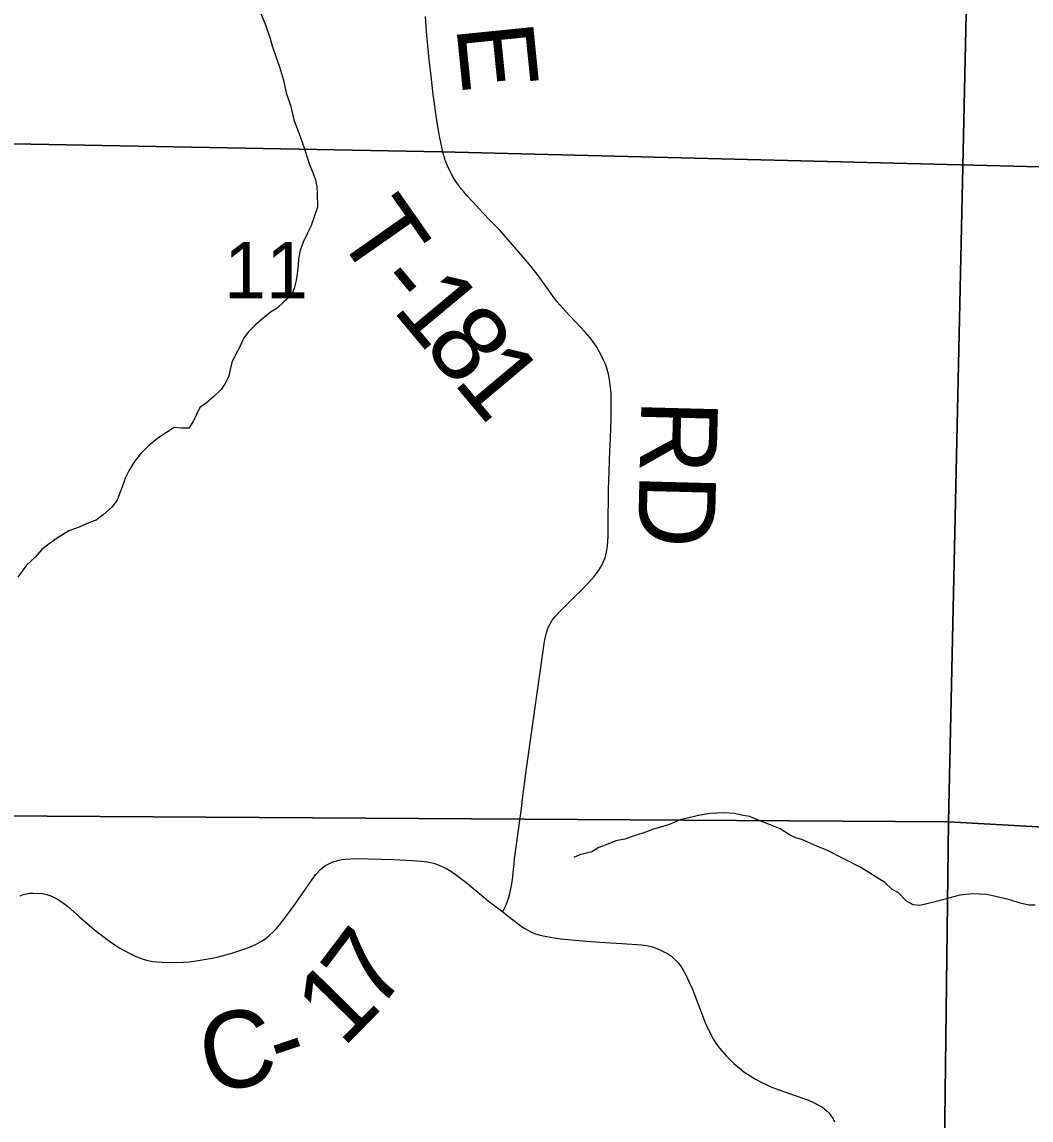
# Model space of a CAD drawing. Extents: x 0 to 34, y 0 to 22.
# Drawn here: x 13.784 to 14.532, y 16.764 to 17.577 of the extents above; entities that cross this region are included whole.
import ezdxf

# ---------------------------------------------------------------- set-up
doc = ezdxf.new("R2010")
doc.units = 0
for name, color, linetype in [('GM_X_Corporation', 7, 'Continuous'), ('GM_X_County_Road', 7, 'Continuous'), ('GM_X_County_Road_Text', 7, 'Continuous'), ('GM_X_Minor_River', 7, 'Continuous'), ('GM_X_Section_Text', 7, 'Continuous'), ('GM_X_Township_Road', 7, 'Continuous'), ('GM_X_Township_Road_Text', 7, 'Continuous')]:
    doc.layers.add(name, color=color, linetype=linetype)

msp = doc.modelspace()

# ---------------------------------------------------------------- linework, layer by layer
at = {"layer": 'GM_X_Corporation'}
for points in [[(13.27416, 17.49656), (14.09544, 17.48114), (14.72599, 17.4654), (14.75606, 17.4645), (15.84263, 17.42782), (15.88436, 17.42688), (16.48069, 17.41608), (16.48857, 17.73917), (16.51683, 18.87067), (16.5174, 18.89349), (16.54748, 18.89293), (16.75204, 18.88908), (16.75322, 19.06144), (16.75475, 19.28374), (16.76523, 20.32799), (16.7661, 20.4), (11.50006, 20.4)], [(16.44192, 14.8642), (16.44975, 15.46263), (16.45161, 15.59641), (16.46108, 16.1288), (16.46029, 16.26174), (16.46891, 16.92454), (16.47027, 17.00356), (16.4704, 17.01044), (16.48069, 17.41608), (15.88436, 17.42688), (15.84263, 17.42782), (14.75606, 17.4645), (14.72599, 17.4654), (14.09544, 17.48114), (13.27416, 17.49656)]]:
    msp.add_lwpolyline(points, dxfattribs=at)
for points in [[(13.4723, 18.00009), (14.4926, 17.9788), (14.47088, 16.98467), (13.4493, 16.99116)], [(14.4926, 17.9788), (15.50037, 17.94467), (15.48158, 16.92817), (14.47088, 16.98467)], [(13.4493, 16.99116), (14.47088, 16.98467), (14.45833, 15.96227), (13.43365, 15.97401)], [(14.47088, 16.98467), (15.48158, 16.92817), (15.46915, 15.91633), (14.45833, 15.96227)]]:
    msp.add_lwpolyline(points, close=True, dxfattribs=at)
at = {"layer": 'GM_X_County_Road'}
msp.add_lwpolyline([(13.78303, 16.92971), (13.78525, 16.93069), (13.78761, 16.93136), (13.7902, 16.93176), (13.7924, 16.9319), (13.79961, 16.93149), (13.80281, 16.93077), (13.80572, 16.92969), (13.80876, 16.92834), (13.81199, 16.92652), (13.81518, 16.92434), (13.81832, 16.92189), (13.82681, 16.91455), (13.83814, 16.90465), (13.84131, 16.90212), (13.84924, 16.89619), (13.85311, 16.89352), (13.85688, 16.89108), (13.8605, 16.88894), (13.86462, 16.88675), (13.8682, 16.88506), (13.87407, 16.8828), (13.87658, 16.88209), (13.8812, 16.88119), (13.88388, 16.88087), (13.88821, 16.88057), (13.892, 16.88046), (13.90407, 16.88065), (13.90815, 16.88096), (13.91335, 16.8816), (13.92521, 16.88367), (13.92986, 16.88466), (13.93533, 16.886), (13.9405, 16.88751), (13.94957, 16.8906), (13.95406, 16.89232), (13.95797, 16.89406), (13.96171, 16.89615), (13.96416, 16.89779), (13.96772, 16.90054), (13.97055, 16.90316), (13.97291, 16.90571), (13.97607, 16.90954), (13.981, 16.91589), (13.98645, 16.92328), (13.9915, 16.93063), (14.00099, 16.94436), (14.00208, 16.94572), (14.00576, 16.94961), (14.00721, 16.95083), (14.00919, 16.95221), (14.01174, 16.95362), (14.01408, 16.95467), (14.01646, 16.95552), (14.01919, 16.95627), (14.02139, 16.9567), (14.02396, 16.95703), (14.03145, 16.95741), (14.0598, 16.95677), (14.07342, 16.95608), (14.0804, 16.9555), (14.08491, 16.95492), (14.08921, 16.95404), (14.09157, 16.95326), (14.09676, 16.95104), (14.09973, 16.94949), (14.10257, 16.94782), (14.10537, 16.94596), (14.1113, 16.94141), (14.11439, 16.93883), (14.12496, 16.93002), (14.12982, 16.92618), (14.14054, 16.91787), (14.14348, 16.91557), (14.15301, 16.90837), (14.15446, 16.90705), (14.15692, 16.90558), (14.15916, 16.90438), (14.16196, 16.90288), (14.1642, 16.90197), (14.1673, 16.90096), (14.17044, 16.90017), (14.17875, 16.89866), (14.18362, 16.89805), (14.20271, 16.89628), (14.21244, 16.89548), (14.22885, 16.89447), (14.24001, 16.89384), (14.24364, 16.89352), (14.24721, 16.89299), (14.25052, 16.89226), (14.25355, 16.89128), (14.25653, 16.89003), (14.25994, 16.88843), (14.26256, 16.88697), (14.26576, 16.88479), (14.26834, 16.88243), (14.27047, 16.88024), (14.27226, 16.87793), (14.27432, 16.87468), (14.27641, 16.87075), (14.27848, 16.86641), (14.28104, 16.86055), (14.28341, 16.85464), (14.29086, 16.83531), (14.29195, 16.83279), (14.29491, 16.82664), (14.29675, 16.82337), (14.299, 16.81989), (14.30118, 16.81696), (14.30636, 16.81096), (14.30848, 16.80876), (14.31213, 16.80528), (14.31597, 16.80203), (14.3193, 16.79948), (14.32388, 16.79633), (14.32788, 16.79391), (14.33202, 16.79167), (14.33577, 16.78988), (14.33928, 16.78836), (14.34519, 16.78609), (14.36707, 16.77831), (14.36972, 16.7772), (14.37602, 16.77405), (14.37743, 16.77318), (14.38105, 16.77027), (14.38225, 16.76899), (14.38377, 16.76704), (14.38531, 16.76463), (14.38644, 16.76241)], dxfattribs=at)
at = {"layer": 'GM_X_Minor_River'}
for points in [[(13.96092, 17.58483), (13.96475, 17.57534), (13.9682, 17.5651), (13.96974, 17.55978), (13.97242, 17.55181), (13.97511, 17.54422), (13.97818, 17.53436), (13.98011, 17.52487), (13.98318, 17.51538), (13.98588, 17.50475), (13.99047, 17.49261), (13.99392, 17.48274), (13.99546, 17.47781), (13.99738, 17.47174), (13.99968, 17.46643), (14.00159, 17.46111), (14.00275, 17.45542), (14.00315, 17.45048), (14.00318, 17.44023), (14.00093, 17.43301), (13.9983, 17.42579), (13.99566, 17.42047), (13.99302, 17.41477), (13.99039, 17.40831), (13.98927, 17.40185), (13.98891, 17.3973), (13.98817, 17.39084), (13.98743, 17.3859), (13.98593, 17.37982), (13.98405, 17.37488), (13.97837, 17.36994), (13.97346, 17.36537), (13.96853, 17.36232), (13.96285, 17.35776), (13.95717, 17.35281), (13.95187, 17.34748), (13.94847, 17.34292), (13.94546, 17.33608), (13.94244, 17.33076), (13.93981, 17.32506), (13.93868, 17.31974), (13.93756, 17.3148), (13.93492, 17.30948), (13.9319, 17.30492), (13.92623, 17.29959), (13.92093, 17.29503), (13.916, 17.2916), (13.9111, 17.28134), (13.90808, 17.2764), (13.90239, 17.27639), (13.89707, 17.27675), (13.88571, 17.26952), (13.87851, 17.26381), (13.87208, 17.25734), (13.86717, 17.25088), (13.86339, 17.2448), (13.86113, 17.23985), (13.8585, 17.23302), (13.85474, 17.22314), (13.85096, 17.21781), (13.84453, 17.2121), (13.83922, 17.2083), (13.83429, 17.20639), (13.82671, 17.20296), (13.81913, 17.20028), (13.81117, 17.19534), (13.80435, 17.19077), (13.79905, 17.18658), (13.79414, 17.18087), (13.78771, 17.17479), (13.78128, 17.16604)], [(14.535, 16.9229), (14.53045, 16.92289), (14.52399, 16.9244), (14.51714, 16.92667), (14.51106, 16.92817), (14.50575, 16.92931), (14.49929, 16.93081), (14.48827, 16.93117), (14.47917, 16.93039), (14.46817, 16.92734), (14.46286, 16.92581), (14.45489, 16.92389), (14.44958, 16.92274), (14.44464, 16.92312), (14.4397, 16.92576), (14.4336, 16.93221), (14.42903, 16.93448), (14.4237, 16.93978), (14.41571, 16.94471), (14.40582, 16.95076), (14.38072, 16.96363), (14.37387, 16.96627), (14.36209, 16.97157), (14.35753, 16.9727), (14.35296, 16.97497), (14.34611, 16.97951), (14.33623, 16.98329), (14.32862, 16.98631), (14.32368, 16.98858), (14.31874, 16.98933), (14.31228, 16.99084), (14.30431, 16.9912), (14.29406, 16.9908), (14.28685, 16.98965), (14.27205, 16.98621), (14.26333, 16.98239), (14.25158, 16.97896), (14.24437, 16.97628), (14.23792, 16.97437), (14.2311, 16.9717), (14.22427, 16.97055), (14.21707, 16.9675), (14.21176, 16.96559), (14.20646, 16.96254), (14.19773, 16.96025), (14.19318, 16.95834)]]:
    msp.add_lwpolyline(points, dxfattribs=at)
at = {"layer": 'GM_X_Township_Road'}
for points in [[(14.08475, 17.56234), (14.08425, 17.5671), (14.08332, 17.58153)], [(14.09796, 17.47485), (14.09611, 17.48112), (14.09365, 17.49285), (14.09169, 17.50447), (14.08907, 17.52368), (14.08741, 17.53713), (14.08585, 17.55185), (14.08475, 17.56234)], [(14.15889, 17.39927), (14.15242, 17.4069), (14.14303, 17.4176), (14.13805, 17.42332), (14.13487, 17.42659), (14.1315, 17.43006), (14.12565, 17.43623), (14.12134, 17.44078), (14.11778, 17.44463), (14.11416, 17.44854), (14.1117, 17.45143), (14.10975, 17.45382), (14.10794, 17.45618), (14.10638, 17.45835), (14.10454, 17.46118), (14.10282, 17.46416), (14.10128, 17.46711), (14.09964, 17.47068), (14.09856, 17.47328), (14.09796, 17.47485)], [(14.14054, 16.91787), (14.14257, 16.92223), (14.14376, 16.92512), (14.14509, 16.92886), (14.14616, 16.93259), (14.14712, 16.93743), (14.14767, 16.94164), (14.14911, 16.95415), (14.1496, 16.95887), (14.15447, 16.99446), (14.15523, 17.00135), (14.15811, 17.02422), (14.16156, 17.04873), (14.17152, 17.11817), (14.17203, 17.12076), (14.1727, 17.12382), (14.1737, 17.12706), (14.17448, 17.12907), (14.17559, 17.13134), (14.17726, 17.13402), (14.17967, 17.13717), (14.18229, 17.14011), (14.18919, 17.14702), (14.19357, 17.15119), (14.19856, 17.15599), (14.20634, 17.16411), (14.20843, 17.16664), (14.21116, 17.17036), (14.21341, 17.17394), (14.21502, 17.177), (14.21638, 17.18021), (14.21703, 17.18227), (14.21755, 17.18457), (14.21811, 17.18904), (14.21856, 17.19631), (14.21873, 17.20335), (14.21902, 17.23098), (14.21937, 17.24416), (14.21967, 17.25264), (14.21994, 17.25938), (14.22034, 17.26877), (14.22065, 17.2768), (14.22085, 17.28263), (14.22099, 17.2927), (14.22078, 17.30171), (14.2206, 17.30471), (14.21973, 17.31227), (14.21914, 17.31536), (14.2185, 17.31803), (14.21747, 17.32147), (14.21662, 17.32381), (14.21524, 17.32689), (14.21405, 17.32957), (14.21235, 17.33277), (14.21021, 17.33638), (14.20757, 17.34029), (14.20499, 17.34365), (14.20172, 17.34749), (14.19426, 17.35551), (14.18704, 17.36317), (14.18296, 17.36771), (14.17925, 17.37221), (14.17585, 17.37677), (14.17299, 17.38085), (14.1711, 17.38355), (14.16811, 17.38767), (14.1661, 17.39044), (14.16213, 17.39545), (14.15889, 17.39927)]]:
    msp.add_lwpolyline(points, dxfattribs=at)

# ---------------------------------------------------------------- texts
at = {"layer": 'GM_X_County_Road_Text'}
for s, rotation, p in [('7', 52.90321, (14.04809, 16.84303)), ('1', 45.50527, (14.02229, 16.8166)), ('C', 11.09943, (13.92204, 16.78285)), ('-', 18.4115, (13.97549, 16.79385))]:
    msp.add_text(s, height=0.05682, rotation=rotation, dxfattribs=at).set_placement(p)
at = {"layer": 'GM_X_Section_Text'}
msp.add_text('11', height=0.041856, rotation=0.00001, dxfattribs=at).set_placement((13.93398, 17.37252))
at = {"layer": 'GM_X_Township_Road_Text'}
for s, height, rotation, p in [('E', 0.05682, 275.76909, (14.10608, 17.57416)), ('T', 0.05682, 304.99764, (14.01565, 17.42106)), ('-', 0.05682, 309.83576, (14.0432, 17.38209)), ('1', 0.05682, 309.80824, (14.05814, 17.36418)), ('8', 0.05682, 309.83275, (14.08057, 17.33727)), ('1', 0.05682, 310.0116, (14.10311, 17.31024)), ('RD', 0.056818, 268.51936, (14.24339, 17.29813))]:
    msp.add_text(s, height=height, rotation=rotation, dxfattribs=at).set_placement(p)

doc.saveas('drawing.dxf')
